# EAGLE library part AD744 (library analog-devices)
Precision, 500 ns Settling BiFET Op Amp Source: http://www.analog.com/static/imported-files/data_sheets/AD744.pdf
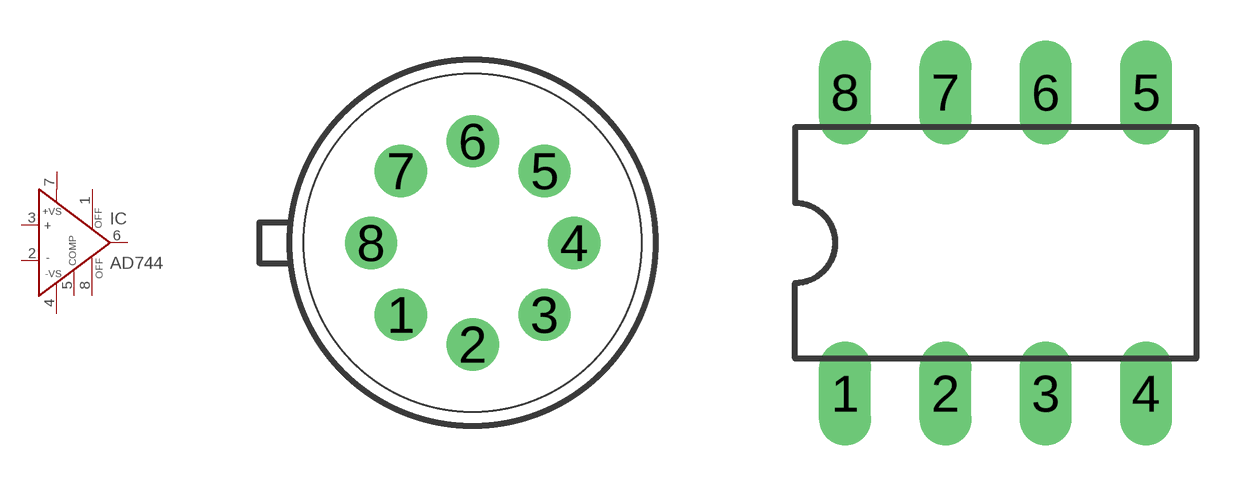
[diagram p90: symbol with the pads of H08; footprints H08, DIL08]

Designator prefix IC

## AD744H (OC_FARNELL: unknown; OC_NEWARK: unknown)  [H08]
1  OFF  pas
2  IN-  in
3  IN+  in
4  -VS  in
5  COMP  pas
6  OUT  out
7  +VS  in
8  OFF  pas

## AD744N (MF: ALTERA CORPORATION; MPN: AD744JNZ; OC_FARNELL: 1438362; OC_NEWARK: 59K4810)  [DIL08]
Pads as for H08

## AD744R (MF: ANALOG DEVICES; MPN: AD744JR; OC_FARNELL: 1651300; OC_NEWARK: 05F7341)  [SO8]
Pads as for H08

## Footprint H08 (pad centres in mm)
8-Lead Metal Can TO-99 (H-8) Source: http://www.analog.com/static/imported-files/data_sheets/AD711.pdf
drill 0.8 pad 1.3 round: 1 -1.796,-1.796; 2 0,-2.54; 3 1.796,-1.796; 4 2.54,0; 5 1.796,1.796; 6 0,2.54; 7 -1.796,1.796; 8 -2.54,0

## Footprint DIL08 (pad centres in mm)
Dual In Line Package
drill 0.813 long: 1 -3.81,-3.81; 2 -1.27,-3.81; 3 1.27,-3.81; 4 3.81,-3.81; 5 3.81,3.81; 6 1.27,3.81; 7 -1.27,3.81; 8 -3.81,3.81

## Footprint SO8 (pad centres in mm)
8-Lead Small Outline IC (SO-8) Source: http://www.analog.com/UploadedFiles/Data_Sheets/703465986AD8611_2_0.pdf
smd 0.6 x 2.2: 1 -1.905,-2.6; 2 -0.635,-2.6; 3 0.635,-2.6; 4 1.905,-2.6; 5 1.905,2.6; 6 0.635,2.6; 7 -0.635,2.6; 8 -1.905,2.6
